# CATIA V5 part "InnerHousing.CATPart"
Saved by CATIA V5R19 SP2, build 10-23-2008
Part number: InnerHousing
Revision: ANY
Definition: UNKNOWN
Nomenclature: InnerHousing
Source: Unknown
Bounding box of the stored display mesh (mm): x -40.823 to 62, y -11 to 20, z -37.204 to 37.204
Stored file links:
  Z:\fausse table rondelle-20220905T211342Z-001\fausse table rondelle\InnerHousing.CATPart
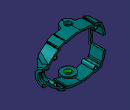
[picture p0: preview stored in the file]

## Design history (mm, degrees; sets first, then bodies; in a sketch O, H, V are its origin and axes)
AxisSystem1: origin (0, 0, 0), X (1, 0, 0), Y (0, 1, 0), Z (0, 0, 1)
Body1 "Verrundung3" (main body)
  Solid1: solid without history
